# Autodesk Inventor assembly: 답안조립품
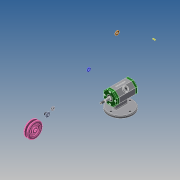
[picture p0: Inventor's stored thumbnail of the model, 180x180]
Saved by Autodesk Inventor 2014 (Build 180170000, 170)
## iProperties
Created: 2021-02
Part Number: 답안조립품
Document SubType Name: Assembly
Designer: kb542
Author: kb542
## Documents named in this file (14)
- C:\Users\kb542\Documents\Inventor\710204V1014\답안조립품.iam
- C:\Users\kb542\Documents\Inventor\710204V1014\본체.ipt
- C:\Users\kb542\Documents\Inventor\710204V1014\710204V1014\V벨트풀리.ipt
- C:\Users\kb542\Documents\Inventor\710204V1014\710204V1014\고무캡.ipt
- C:\Users\kb542\Documents\Inventor\710204V1014\710204V1014\너트 M8.ipt
- C:\Users\kb542\Documents\Inventor\710204V1014\710204V1014\뒤커버.ipt
- C:\Users\kb542\Documents\Inventor\710204V1014\710204V1014\베어링 15 x 32 x 9.ipt
- C:\Users\kb542\Documents\Inventor\710204V1014\710204V1014\볼트 M4 x 12.ipt
- C:\Users\kb542\Documents\Inventor\710204V1014\710204V1014\스프링와셔 8.ipt
- C:\Users\kb542\Documents\Inventor\710204V1014\710204V1014\앞커버.ipt
- C:\Users\kb542\Documents\Inventor\710204V1014\710204V1014\오일 실 15 25 7.ipt
- C:\Users\kb542\Documents\Inventor\710204V1014\710204V1014\와셔 8x17.ipt
- C:\Users\kb542\Documents\Inventor\710204V1014\710204V1014\축.ipt
- C:\Users\kb542\Documents\Inventor\710204V1014\710204V1014\키 3 x 3 x 12.ipt
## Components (2 placed, 2 different names)
1. V벨트풀리:1
2. 고무캡:1
